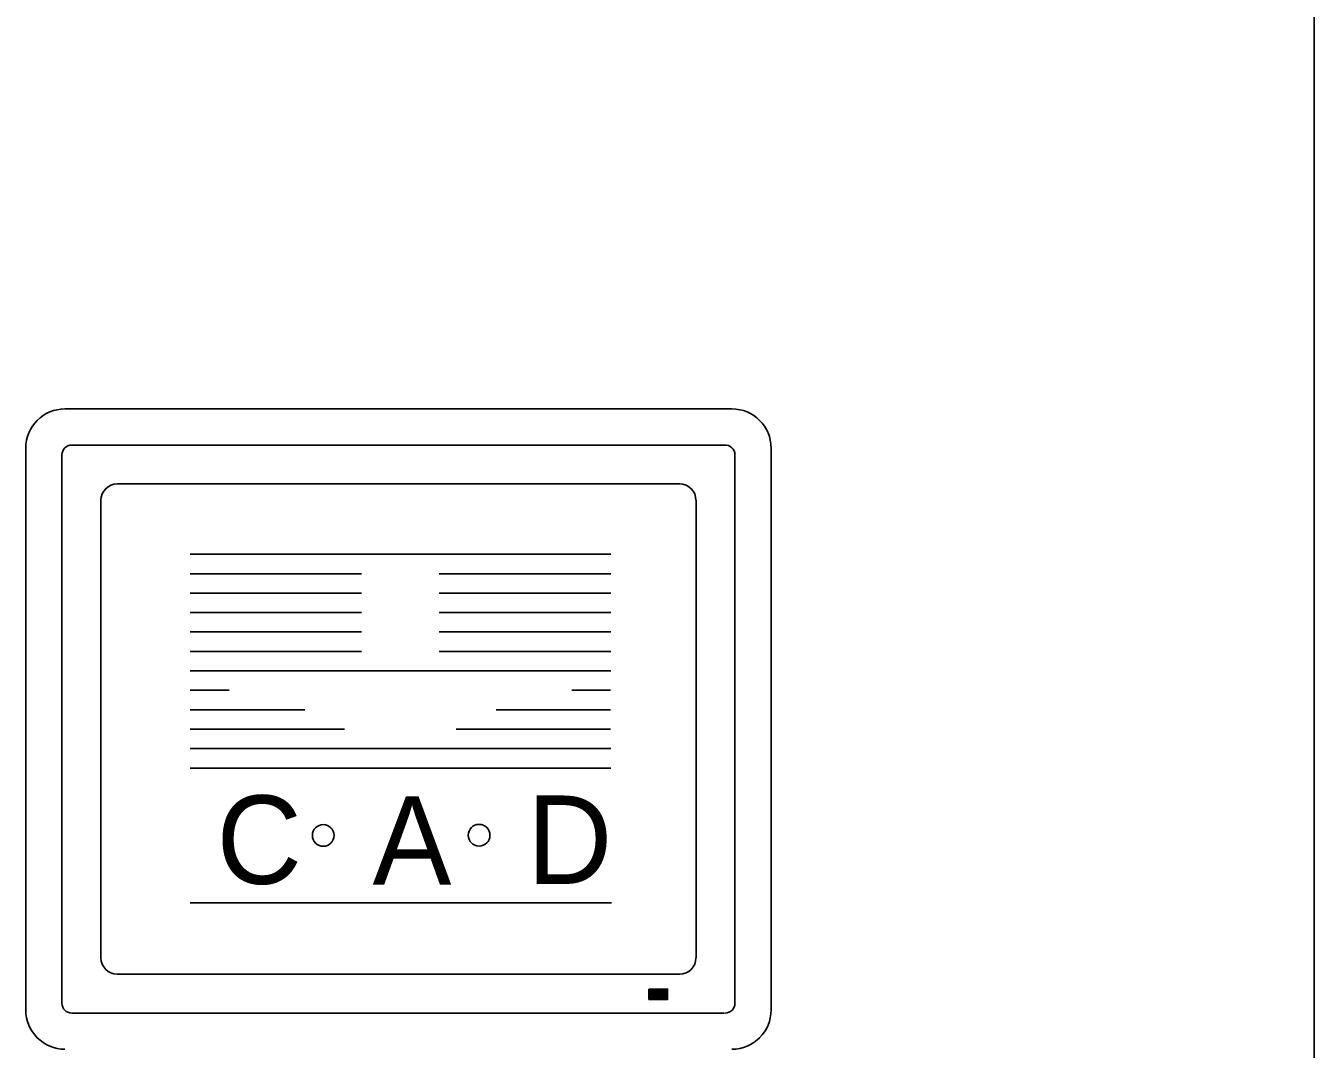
# Model space of a CAD drawing. Extents: x 22369.6 to 22428.3, y 22369.6 to 22415.
# Drawn here: x 22421.062 to 22423.952, y 22372.404 to 22374.7 of the extents above; entities that cross this region are included whole.
import ezdxf

# ---------------------------------------------------------------- set-up
doc = ezdxf.new("R2010")
doc.units = 0
for name, color, linetype in [('Level 2', 7, 'Continuous'), ('Level 3', 7, 'Continuous'), ('Level 5', 7, 'Continuous'), ('Level 9', 7, 'Continuous')]:
    doc.layers.add(name, color=color, linetype=linetype)

msp = doc.modelspace()

# ---------------------------------------------------------------- linework, layer by layer
at = {"layer": 'Level 2'}
for p, q in [((22421.2673, 22373.6719), (22422.529, 22373.6719)), ((22421.2307, 22372.6088), (22421.2307, 22373.6353)), ((22422.5657, 22372.6088), (22422.5657, 22373.6353)), ((22421.2673, 22372.5721), (22422.529, 22372.5721)), ((22422.4598, 22372.5376), (22422.5017, 22372.5376)), ((22422.4598, 22372.5364), (22422.5017, 22372.5364)), ((22422.4598, 22372.5351), (22422.5017, 22372.5351)), ((22422.4598, 22372.5336), (22422.5017, 22372.5336)), ((22422.4598, 22372.5323), (22422.5017, 22372.5323)), ((22422.4598, 22372.5311), (22422.5017, 22372.5311)), ((22422.4598, 22372.5298), (22422.5017, 22372.5298)), ((22422.4598, 22372.5284), (22422.5017, 22372.5284)), ((22422.4598, 22372.5271), (22422.5017, 22372.5271)), ((22422.4598, 22372.5258), (22422.5017, 22372.5258)), ((22422.4598, 22372.5244), (22422.5017, 22372.5244)), ((22422.4598, 22372.5231), (22422.5017, 22372.5231)), ((22422.4598, 22372.5219), (22422.5017, 22372.5219)), ((22422.4598, 22372.5204), (22422.5017, 22372.5204)), ((22422.4598, 22372.5191), (22422.5017, 22372.5191)), ((22422.4598, 22372.5179), (22422.5017, 22372.5179)), ((22422.4598, 22372.5166), (22422.5017, 22372.5166))]:
    msp.add_line(p, q, dxfattribs=at)
msp.add_lwpolyline([(22422.4598, 22372.5386), (22422.5017, 22372.5386), (22422.5017, 22372.5154), (22422.4598, 22372.5154)], close=True, dxfattribs=at)
for centre in [(22421.7294, 22372.8835), (22422.0789, 22372.8837)]:
    msp.add_circle(centre, 0.0244, dxfattribs=at)
for centre, start, end in [((22421.2673, 22373.6352), 90, 180), ((22422.5289, 22373.6352), 0, 90), ((22421.2673, 22372.6088), 180, 270), ((22422.5289, 22372.6088), 270, 0)]:
    msp.add_arc(centre, 0.0367, start, end, dxfattribs=at)
at = {"layer": 'Level 3'}
for p, q in [((22421.1502, 22373.8404), (22422.6462, 22373.8404)), ((22421.0622, 22372.4916), (22421.0622, 22373.7524)), ((22421.1653, 22373.7593), (22422.6295, 22373.7593)), ((22422.7342, 22372.4916), (22422.7342, 22373.7524)), ((22421.1433, 22372.5069), (22421.1433, 22373.7373)), ((22422.653, 22372.5069), (22422.653, 22373.7373)), ((22421.1653, 22372.4849), (22422.6295, 22372.4849))]:
    msp.add_line(p, q, dxfattribs=at)
for centre, radius, start, end in [((22421.1501, 22373.7524), 0.088, 90, 180), ((22422.6461, 22373.7524), 0.088, 0, 90), ((22421.1653, 22373.7372), 0.022, 90, 180), ((22422.6309, 22373.7372), 0.022, 0, 93.8704), ((22421.1653, 22372.5068), 0.022, 180, 270), ((22422.6309, 22372.5068), 0.022, 270, 0), ((22421.1501, 22372.4917), 0.088, 180, 270), ((22422.6461, 22372.4917), 0.088, 270, 0)]:
    msp.add_arc(centre, radius, start, end, dxfattribs=at)
at = {"layer": 'Level 5'}
for p, q in [((22421.4308, 22373.5141), (22422.3742, 22373.5141)), ((22421.4308, 22373.4704), (22421.8153, 22373.4704)), ((22421.9895, 22373.4704), (22422.3742, 22373.4704)), ((22421.4308, 22373.4269), (22421.8153, 22373.4269)), ((22421.9895, 22373.4269), (22422.3742, 22373.4269)), ((22421.4308, 22373.3834), (22421.8153, 22373.3834)), ((22421.9895, 22373.3834), (22422.3742, 22373.3834)), ((22421.4308, 22373.3398), (22421.8153, 22373.3398)), ((22421.9895, 22373.3398), (22422.3742, 22373.3398)), ((22421.4308, 22373.2961), (22421.8153, 22373.2961)), ((22421.9895, 22373.2961), (22422.3742, 22373.2961)), ((22421.4308, 22373.2524), (22422.3742, 22373.2524)), ((22421.4308, 22373.2091), (22421.518, 22373.2091)), ((22422.374, 22373.2091), (22422.2868, 22373.2091)), ((22421.4308, 22373.1654), (22421.6878, 22373.1654)), ((22422.374, 22373.1654), (22422.117, 22373.1654)), ((22421.4308, 22373.1219), (22421.7772, 22373.1219)), ((22422.374, 22373.1219), (22422.0277, 22373.1219)), ((22421.4308, 22373.0783), (22422.3742, 22373.0783)), ((22421.4308, 22373.0346), (22422.3742, 22373.0346)), ((22421.4308, 22372.7321), (22422.3758, 22372.7321))]:
    msp.add_line(p, q, dxfattribs=at)
at = {"layer": 'Level 9'}
msp.add_lwpolyline([(22423.9525, 22370.288), (22423.9525, 22414.288)], dxfattribs=at)

# ---------------------------------------------------------------- texts
at = {"layer": 'Level 5'}
for s, p in [('C', (22421.49, 22372.7746)), ('A', (22421.84, 22372.7729)), ('D', (22422.1863, 22372.7746))]:
    msp.add_text(s, height=0.1984, dxfattribs=at).set_placement(p)

doc.saveas('drawing.dxf')
